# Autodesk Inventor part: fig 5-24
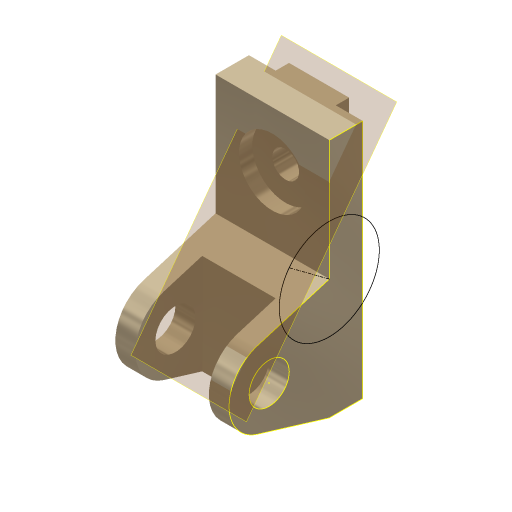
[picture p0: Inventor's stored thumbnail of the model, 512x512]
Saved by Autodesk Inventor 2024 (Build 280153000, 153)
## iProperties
Shininess: 65.0
Angle Display Precision: 2
Document Length Units: 11269
Document Angle Units: 11279
Document Time Units: 11290
Document Mass Units: 11283
Document Length Units Precision: 3
Document Angle Units Precision: 2
Compacted: False
Created: 2001-11
Part Number: fig 5-24
Document SubType Name: Modeling
Designer: Renu Muthoo
Density: 1 g/cm^3
Material: Generic
Appearance: Metal-Titanium (Polished)
Density: 0.0
Volumn: 0.0
Area: 0.0
PropertySet Name: Model Information
Control State: 0
Master: False
Checked Out: False
Author: Renu Muthoo
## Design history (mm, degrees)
sketch "Sketch2"
  geometry: L1 (33.257, 104.664)-(33.257, -75.336); L2 (33.257, -75.336)-(8.257, -75.336); L3 (8.257, -75.336)-(-45.451, -59.045); L4 (-45.451, -1.628)-(8.257, 14.664); L5 (8.257, 14.664)-(8.257, 104.664); L6 (8.257, 104.664)-(33.257, 104.664); C1 r 15 at (-36.743, -30.336); A1 r 30 centre (-36.743, -30.336) between (-45.451, -1.628) and (-45.451, -59.045)
  constraints: 12 end point, 2 centre point, 2 equal length, 2 parallel, 2 point on circle, 2 tangent, 1 coincident, 1 perpendicular, 1 vertical
  dimensions: "d0" = 180 distance of L1.start L1.end; "d1" = 30 radius of A1; "d2" = 25 distance of L5.end L1.start; "d3" = 45 distance from line of L2 A1.centre; "d4" = 70 distance from line of L1 A1.centre; "d5" = 30 diameter of C1
extrude "Extrusion1" new body sketch "Sketch2" distance "d6" = 85; taper "d7" = 0 deg
workplane "Work Plane1"
sketch "Sketch3"
  geometry: L1 (15, 62.364)-(70, 62.364); L2 (70, 62.364)-(70, -52.386); L3 (70, -52.386)-(15, -52.386); L4 (15, -52.386)-(15, 62.364); L5 (0, -45)-(0, -28.708) reference
  constraints: 8 end point, 2 parallel, 1 horizontal, 1 perpendicular
  dimensions: "d8" = 55 distance of L1.start L1.end; "d9" = 15 distance between parallel lines of L5 L4
extrude "Extrusion2" cut sketch "Sketch3" distance "d10" = 50; taper "d11" = 0 deg
sketch "Sketch4"
  geometry: L1 (0, 25)-(85, 25) reference; L2 (0, 0)-(0, 25) reference; L3 (20, 25)-(65, 25); L4 (65, 25)-(65, 35); L5 (65, 35)-(20, 35); L6 (20, 35)-(20, 25)
  constraints: 8 end point, 2 parallel, 1 horizontal, 1 perpendicular, 1 point on line
  dimensions: "d12" = 45 distance of L4.end L5.end; "d13" = 10 distance of L3.end L4.end; "d14" = 20 distance between parallel lines of L2 L6
extrude "Extrusion3" join sketch "Sketch4" stored distance "d15" = 50; taper "d16" = 0 deg
sketch "Sketch5"
  geometry: L1 (85, 0)-(85, 90) reference; L2 (0, 90)-(85, 90) reference; 1 further point
  dimensions: "d17" = 42 distance from line of L2 point (42.5, 48); "d18" = 42.5 distance from line of L1 point (42.5, 48)
hole "Hole1" sketch "Sketch5" diameter "d19" = 20; stored, may be unused: countersink angle "d23" = 82 deg, drill point angle "d25" = 118 deg; dims "d20" = 6, "d21" = 50, "d22" = 10, "d24" = 8
sketch "Sketch8"
  geometry: L1 (75.336, 33.257)-(75.336, 8.257) reference; L2 (-104.664, 33.257)-(75.336, 33.257) reference; L3 (-104.664, 8.257)-(-104.664, 33.257) reference; L4 (-14.664, 8.257)-(-104.664, 8.257) reference; L5 (1.628, -45.451)-(-14.664, 8.257) reference; L6 (75.336, 8.257)-(59.045, -45.451) reference; C1 r 15 at (30.336, -36.743) reference; C2 r 37.437 at (-14.664, 8.257); A1 r 30 centre (30.336, -36.743) between (1.628, -45.451) and (59.045, -45.451) reference
  constraints: 1 centre point, 1 coincident
sketch "Sketch9"
  geometry: L1 (75.336, 33.257)-(75.336, 8.257) reference; L2 (-14.664, 8.257)-(-104.664, 8.257) reference; L3 (1.628, -45.451)-(-14.664, 8.257) reference; L4 (75.336, 8.257)-(59.045, -45.451) reference; L5 (-14.664, 8.257)-(-37, -21.743); C1 r 15 at (30.336, -36.743) reference; A1 r 30 centre (30.336, -36.743) between (1.628, -45.451) and (59.045, -45.451) reference
  constraints: 2 end point
workplane "Work Plane11"
body "Solid1"
node "Sketch1"
